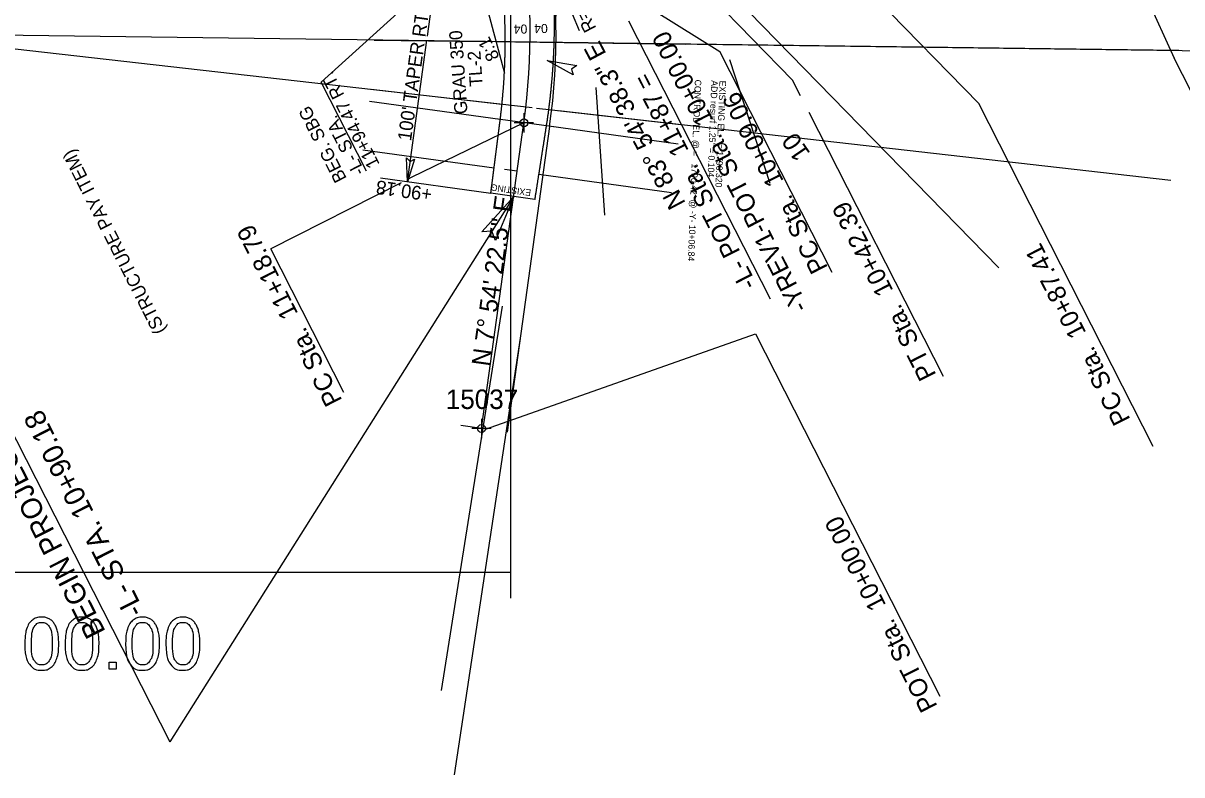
# Model space of a CAD drawing. Extents: x 557583 to 560285, y 513145 to 516544.
# Drawn here: x 559211.5 to 559657.8, y 515111.5 to 515400.9 of the extents above; entities that cross this region are included whole.
import ezdxf

# ---------------------------------------------------------------- set-up
doc = ezdxf.new("R2010")
doc.units = 0
for name, color, linetype in [('COGO Default Chain', 7, 'Continuous'), ('Default', 7, 'Continuous'), ('Exist Environmental Wetland Boundary', 7, 'Continuous'), ('Exist Environmental Wetland Boundary Cogo Comment', 7, 'Continuous'), ('Exist Environmental Wetland Boundary Cogo Point CELL', 7, 'Continuous'), ('Exist Hydro Jurisdictional Stream or Body of Water NEU Mitigable Cogo Comment', 7, 'Continuous'), ('Exist Hydro Jurisdictional Stream or Body of Water NEU Mitigable Cogo Elevation', 7, 'Continuous'), ('Exist Hydro Swamp or Marsh', 7, 'Continuous'), ('Prop Dimension', 7, 'Continuous'), ('Prop DSN Text', 7, 'Continuous'), ('Prop EOT', 7, 'Continuous'), ('Prop Guardrail Anchor Unit CELL', 7, 'Continuous'), ('Prop Paved Shoulder', 7, 'Continuous'), ('Prop Superelevation Label', 7, 'Continuous'), ('Prop Terminator CELL', 7, 'Continuous'), ('Scratch_Level_0', 7, 'Continuous'), ('Scratch_Level_2', 7, 'Continuous'), ('Scratch_Level_3', 7, 'Continuous'), ('Scratch_Level_4', 7, 'Continuous'), ('Scratch_Level_7', 7, 'Continuous'), ('Scratch_Level_8', 7, 'Continuous')]:
    doc.layers.add(name, color=color, linetype=linetype)

msp = doc.modelspace()

# ---------------------------------------------------------------- linework, layer by layer
at = {"layer": 'COGO Default Chain'}
for p, q in [((559404.4, 515366.25), (559404.4, 515358.75)), ((559408.15, 515362.5), (559400.65, 515362.5)), ((559388.06, 515248.59), (559388.06, 515241.09)), ((559391.81, 515244.84), (559384.31, 515244.84))]:
    msp.add_line(p, q, dxfattribs=at)
msp.add_arc((559156.78, 515396.89), 250, 352.0938, 26.9819, dxfattribs=at)
at = {"layer": 'Default'}
for p, q in [((559399.28, 515447.65), (559399.28, 515179.47)), ((559105.95, 515189.47), (559399.28, 515189.47))]:
    msp.add_line(p, q, dxfattribs=at)
at = {"layer": 'Exist Environmental Wetland Boundary'}
msp.add_line((559388.06, 515244.84), (559380.14, 515245.94), dxfattribs=at)
msp.add_line((559388.06, 515244.84), (559380.14, 515245.94), dxfattribs=at)
at = {"layer": 'Exist Environmental Wetland Boundary Cogo Point CELL'}
for p, q in [((559590.29, 515529.56), (559654.86, 515387.43)), ((559443.12, 515445.39), (559507.89, 515378.97)), ((559510.6, 515440.68), (559579.6, 515369.93)), ((559425.75, 515397.97), (559411.89, 515431.29)), ((559413.51, 515431.46), (559479.86, 515389.93)), ((559499.36, 515294.58), (559444.86, 515401.63)), ((559523.19, 515304.83), (559479.86, 515389.93)), ((559701.49, 515295.84), (559654.86, 515387.43)), ((559511, 515372.86), (559507.89, 515378.97)), ((559646.83, 515237.87), (559579.6, 515369.93)), ((559565.98, 515264.88), (559514.27, 515366.44)), ((559404.4, 515362.5), (559361, 515341.43)), ((559361, 515341.43), (559360.02, 515340.93)), ((559357.1, 515339.44), (559306.95, 515313.98)), ((559335.08, 515258.72), (559306.95, 515313.98)), ((559389.55, 515244.63), (559493.66, 515281.3)), ((559493.66, 515281.3), (559564.68, 515141.8))]:
    msp.add_line(p, q, dxfattribs=at)
for centre in [(559404.4, 515362.5), (559404.4, 515362.5), (559388.06, 515244.84), (559388.06, 515244.84), (559388.06, 515244.84)]:
    msp.add_circle(centre, 1.5, dxfattribs=at)
at = {"layer": 'Exist Hydro Jurisdictional Stream or Body of Water NEU Mitigable Cogo Elevation'}
msp.add_line((559388.06, 515244.84), (559404.4, 515362.5), dxfattribs=at)
msp.add_arc((559156.78, 515396.89), 250, 352.0938, 26.9819, dxfattribs=at)
at = {"layer": 'Exist Hydro Swamp or Marsh'}
msp.add_line((559401.81, 515343.89), (559396.86, 515344.58), dxfattribs=at)
msp.add_line((559401.81, 515343.89), (559396.86, 515344.58), dxfattribs=at)
at = {"layer": 'Prop Dimension'}
for p, q in [((559389.76, 515435.62), (559326.3, 515378.18)), ((559367.26, 515395.81), (559371.85, 515428.86)), ((559359.49, 515339.85), (559367.06, 515394.34)), ((559343.77, 515343.92), (559326.3, 515378.18)), ((559349.18, 515341.28), (559391.65, 515335.39)), ((559400.46, 515334.16), (559267.96, 515124.18)), ((559191.37, 515274.61), (559267.96, 515124.18))]:
    msp.add_line(p, q, dxfattribs=at)
at = {"layer": 'Prop DSN Text'}
for p, q in [((559404.4, 515366.25), (559404.4, 515358.75)), ((559408.15, 515362.5), (559400.65, 515362.5))]:
    msp.add_line(p, q, dxfattribs=at)
msp.add_arc((559156.78, 515396.89), 250, 352.0938, 26.9819, dxfattribs=at)
at = {"layer": 'Prop EOT'}
msp.add_line((559408.66, 515333.02), (559391.65, 515335.39), dxfattribs=at)
msp.add_arc((559448.16, 515398.31), 32, 115.7408, 179.4343, dxfattribs=at)
for points in [[(559415.56, 515383.31), (559415.61, 515384.01), (559415.65, 515384.71), (559415.7, 515385.41), (559415.74, 515386.1), (559415.78, 515386.8), (559415.82, 515387.5), (559415.85, 515388.2), (559415.89, 515388.9), (559415.92, 515389.6), (559415.95, 515390.3), (559415.98, 515391), (559416, 515391.7), (559416.03, 515392.4), (559416.05, 515393.11), (559416.07, 515393.81), (559416.09, 515394.51), (559416.11, 515395.21), (559416.12, 515395.91), (559416.14, 515396.61), (559416.15, 515397.31), (559416.16, 515398.01), (559416.17, 515398.71), (559416.17, 515399.41), (559416.17, 515400.11), (559416.18, 515400.82), (559416.18, 515401.52), (559416.17, 515402.22), (559416.17, 515402.92), (559416.17, 515403.62), (559416.16, 515404.32), (559416.15, 515405.02), (559416.14, 515405.73), (559416.12, 515406.43), (559416.11, 515407.13), (559416.09, 515407.83), (559416.07, 515408.53), (559416.05, 515409.23), (559416.03, 515409.93), (559416, 515410.63), (559415.98, 515411.34), (559415.95, 515412.04), (559415.92, 515412.74), (559415.89, 515413.44), (559415.85, 515414.14), (559415.82, 515414.84), (559415.78, 515415.54), (559415.74, 515416.24), (559415.7, 515416.94), (559415.65, 515417.64), (559415.61, 515418.34), (559415.56, 515419.04), (559415.51, 515419.75), (559415.46, 515420.45), (559415.41, 515421.15), (559415.35, 515421.85), (559415.3, 515422.55), (559415.24, 515423.25), (559415.18, 515423.95), (559415.11, 515424.64), (559415.05, 515425.34), (559414.98, 515426.04), (559414.92, 515426.74), (559414.85, 515427.44), (559414.77, 515428.14), (559414.7, 515428.84), (559414.62, 515429.54), (559414.55, 515430.24), (559414.47, 515430.93), (559414.39, 515431.63), (559414.3, 515432.33), (559414.22, 515433.03), (559414.13, 515433.72), (559413.95, 515435.12)], [(559397, 515384.28), (559397.02, 515384.93), (559397.05, 515385.58), (559397.07, 515386.23), (559397.09, 515386.88), (559397.11, 515387.53), (559397.12, 515388.18), (559397.14, 515388.83), (559397.15, 515389.48), (559397.16, 515390.13), (559397.17, 515390.78), (559397.18, 515391.43), (559397.19, 515392.08), (559397.19, 515392.73), (559397.2, 515393.38), (559397.2, 515394.03), (559397.2, 515394.68), (559397.19, 515395.33), (559397.19, 515395.98), (559397.18, 515396.63), (559397.18, 515397.28), (559397.17, 515397.93), (559397.16, 515398.58), (559397.14, 515399.23), (559397.13, 515399.88), (559397.11, 515400.53), (559397.09, 515401.18), (559397.07, 515401.83), (559397.05, 515402.48), (559397.03, 515403.12), (559397, 515403.77), (559396.98, 515404.42), (559396.95, 515405.07), (559396.92, 515405.72), (559396.89, 515406.37), (559396.85, 515407.02), (559396.82, 515407.67), (559396.78, 515408.31), (559396.74, 515408.96), (559396.7, 515409.61), (559396.66, 515410.26), (559396.61, 515410.91), (559396.57, 515411.55), (559396.52, 515412.2), (559396.47, 515412.85), (559396.42, 515413.5), (559396.36, 515414.14), (559396.31, 515414.79), (559396.25, 515415.44), (559396.19, 515416.08), (559396.13, 515416.73), (559396.07, 515417.38), (559396.01, 515418.02), (559395.94, 515418.67), (559395.88, 515419.31), (559395.81, 515419.96), (559395.74, 515420.6), (559395.66, 515421.25), (559395.59, 515421.89), (559395.51, 515422.54), (559395.44, 515423.18), (559395.36, 515423.83), (559395.28, 515424.47), (559395.19, 515425.11), (559395.11, 515425.76), (559395.02, 515426.4), (559394.93, 515427.04), (559394.84, 515427.69), (559394.75, 515428.33), (559394.66, 515428.97), (559394.56, 515429.61), (559394.47, 515430.25), (559394.37, 515430.9), (559394.17, 515432.18)], [(559391.65, 515335.39), (559391.73, 515336.06), (559391.82, 515336.73), (559391.91, 515337.4), (559391.99, 515338.07), (559392.08, 515338.74), (559392.16, 515339.41), (559392.25, 515340.08), (559392.33, 515340.75), (559392.42, 515341.42), (559392.5, 515342.09), (559392.59, 515342.76), (559392.68, 515343.43), (559392.76, 515344.1), (559392.85, 515344.77), (559392.93, 515345.44), (559393.02, 515346.11), (559393.1, 515346.78), (559393.19, 515347.45), (559393.27, 515348.12), (559393.36, 515348.79), (559393.45, 515349.46), (559393.53, 515350.13), (559393.62, 515350.8), (559393.7, 515351.47), (559393.79, 515352.14), (559393.87, 515352.81), (559393.96, 515353.48), (559394.04, 515354.15), (559394.13, 515354.82), (559394.22, 515355.49), (559394.3, 515356.17), (559394.39, 515356.84), (559394.47, 515357.51), (559394.56, 515358.18), (559394.64, 515358.85), (559394.73, 515359.52), (559394.82, 515360.19), (559394.9, 515360.86), (559394.99, 515361.53), (559395.07, 515362.2), (559395.16, 515362.87), (559395.24, 515363.54), (559395.33, 515364.19), (559395.41, 515364.84), (559395.48, 515365.48), (559395.56, 515366.13), (559395.64, 515366.78), (559395.71, 515367.42), (559395.78, 515368.07), (559395.85, 515368.72), (559395.92, 515369.36), (559395.98, 515370.01), (559396.05, 515370.66), (559396.11, 515371.31), (559396.17, 515371.95), (559396.23, 515372.6), (559396.29, 515373.25), (559396.34, 515373.9), (559396.4, 515374.55), (559396.45, 515375.19), (559396.5, 515375.84), (559396.55, 515376.49), (559396.6, 515377.14), (559396.64, 515377.79), (559396.68, 515378.44), (559396.73, 515379.09), (559396.77, 515379.74), (559396.8, 515380.39), (559396.84, 515381.03), (559396.87, 515381.68), (559396.91, 515382.33), (559396.94, 515382.98), (559396.97, 515383.63), (559397, 515384.28)], [(559408.67, 515333.02), (559408.77, 515333.69), (559408.87, 515334.36), (559408.98, 515335.03), (559409.08, 515335.69), (559409.19, 515336.36), (559409.29, 515337.03), (559409.4, 515337.7), (559409.5, 515338.36), (559409.61, 515339.03), (559409.71, 515339.7), (559409.81, 515340.37), (559409.92, 515341.04), (559410.02, 515341.7), (559410.13, 515342.37), (559410.23, 515343.04), (559410.34, 515343.71), (559410.44, 515344.37), (559410.55, 515345.04), (559410.65, 515345.71), (559410.75, 515346.38), (559410.86, 515347.04), (559410.96, 515347.71), (559411.07, 515348.38), (559411.17, 515349.05), (559411.28, 515349.71), (559411.38, 515350.38), (559411.49, 515351.05), (559411.59, 515351.72), (559411.69, 515352.39), (559411.8, 515353.05), (559411.9, 515353.72), (559412.01, 515354.39), (559412.11, 515355.06), (559412.22, 515355.72), (559412.32, 515356.39), (559412.43, 515357.06), (559412.53, 515357.73), (559412.63, 515358.39), (559412.74, 515359.06), (559412.84, 515359.73), (559412.95, 515360.4), (559413.05, 515361.07), (559413.16, 515361.75), (559413.26, 515362.44), (559413.37, 515363.13), (559413.47, 515363.82), (559413.57, 515364.52), (559413.67, 515365.21), (559413.76, 515365.9), (559413.86, 515366.6), (559413.95, 515367.29), (559414.04, 515367.98), (559414.13, 515368.68), (559414.22, 515369.37), (559414.3, 515370.07), (559414.39, 515370.76), (559414.47, 515371.46), (559414.55, 515372.15), (559414.62, 515372.85), (559414.7, 515373.54), (559414.77, 515374.24), (559414.84, 515374.94), (559414.91, 515375.63), (559414.98, 515376.33), (559415.05, 515377.03), (559415.11, 515377.72), (559415.18, 515378.42), (559415.24, 515379.12), (559415.29, 515379.82), (559415.35, 515380.51), (559415.41, 515381.21), (559415.46, 515381.91), (559415.51, 515382.61), (559415.56, 515383.31)]]:
    msp.add_spline(points, degree=3, dxfattribs=at)
at = {"layer": 'Prop Paved Shoulder'}
msp.add_line((559390.29, 515406.56), (559396.87, 515381.68), dxfattribs=at)
at = {"layer": 'Prop Terminator CELL'}
for points in [[(559362.27, 515348.55), (559359.49, 515339.85), (559359.15, 515349.04), (559360.58, 515347.68)], [(559388.24, 515320.59), (559400.46, 515334.16), (559393.51, 515317.15), (559392.03, 515320.8)]]:
    msp.add_lwpolyline(points, close=True, dxfattribs=at)
at = {"layer": 'Scratch_Level_0'}
msp.add_lwpolyline([(559244.58, 515152.12), (559244.58, 515154.91), (559247.37, 515154.91), (559247.37, 515152.12), (559244.58, 515152.12)], dxfattribs=at)
for points in [[(559212.14, 515161.98), (559212.14, 515165.53), (559212.87, 515167.69), (559213.6, 515169.86), (559215.04, 515171.03), (559216.48, 515172.19), (559218.66, 515172.19), (559220.27, 515172.19), (559221.49, 515171.55), (559222.7, 515170.9), (559223.49, 515169.68), (559224.28, 515168.46), (559224.73, 515166.71), (559225.18, 515164.95), (559225.18, 515161.98), (559225.18, 515158.46), (559224.45, 515156.3), (559223.73, 515154.13), (559222.29, 515152.96), (559220.86, 515151.78), (559218.66, 515151.78), (559215.77, 515151.78), (559214.12, 515153.85), (559212.14, 515156.35), (559212.14, 515161.98)], [(559227.68, 515161.98), (559227.68, 515165.53), (559228.41, 515167.69), (559229.14, 515169.86), (559230.57, 515171.03), (559232.01, 515172.19), (559234.19, 515172.19), (559235.8, 515172.19), (559237.02, 515171.55), (559238.24, 515170.9), (559239.02, 515169.68), (559239.81, 515168.46), (559240.26, 515166.71), (559240.71, 515164.95), (559240.71, 515161.98), (559240.71, 515158.46), (559239.99, 515156.3), (559239.27, 515154.13), (559237.83, 515152.96), (559236.39, 515151.78), (559234.19, 515151.78), (559231.3, 515151.78), (559229.65, 515153.85), (559227.68, 515156.35), (559227.68, 515161.98)], [(559250.97, 515161.98), (559250.97, 515165.53), (559251.7, 515167.69), (559252.43, 515169.86), (559253.87, 515171.03), (559255.31, 515172.19), (559257.49, 515172.19), (559259.1, 515172.19), (559260.31, 515171.55), (559261.53, 515170.9), (559262.32, 515169.68), (559263.1, 515168.46), (559263.55, 515166.71), (559264, 515164.95), (559264, 515161.98), (559264, 515158.46), (559263.28, 515156.3), (559262.56, 515154.13), (559261.12, 515152.96), (559259.68, 515151.78), (559257.49, 515151.78), (559254.6, 515151.78), (559252.95, 515153.85), (559250.97, 515156.35), (559250.97, 515161.98)], [(559266.5, 515161.98), (559266.5, 515165.53), (559267.23, 515167.69), (559267.96, 515169.86), (559269.4, 515171.03), (559270.84, 515172.19), (559273.02, 515172.19), (559274.63, 515172.19), (559275.85, 515171.55), (559277.06, 515170.9), (559277.85, 515169.68), (559278.64, 515168.46), (559279.09, 515166.71), (559279.54, 515164.95), (559279.54, 515161.98), (559279.54, 515158.46), (559278.81, 515156.3), (559278.09, 515154.13), (559276.65, 515152.96), (559275.22, 515151.78), (559273.02, 515151.78), (559270.13, 515151.78), (559268.48, 515153.85), (559266.5, 515156.35), (559266.5, 515161.98)], [(559214.67, 515161.98), (559214.67, 515157.05), (559215.82, 515155.42), (559216.97, 515153.8), (559218.66, 515153.8), (559220.35, 515153.8), (559221.5, 515155.43), (559222.65, 515157.06), (559222.65, 515161.98), (559222.65, 515166.92), (559221.5, 515168.54), (559220.35, 515170.17), (559218.63, 515170.17), (559216.95, 515170.17), (559215.94, 515168.73), (559214.67, 515166.91), (559214.67, 515161.98)], [(559230.21, 515161.98), (559230.21, 515157.05), (559231.36, 515155.42), (559232.51, 515153.8), (559234.19, 515153.8), (559235.88, 515153.8), (559237.03, 515155.43), (559238.18, 515157.06), (559238.18, 515161.98), (559238.18, 515166.92), (559237.03, 515168.54), (559235.88, 515170.17), (559234.17, 515170.17), (559232.48, 515170.17), (559231.47, 515168.73), (559230.21, 515166.91), (559230.21, 515161.98)], [(559253.5, 515161.98), (559253.5, 515157.05), (559254.65, 515155.42), (559255.8, 515153.8), (559257.49, 515153.8), (559259.17, 515153.8), (559260.32, 515155.43), (559261.47, 515157.06), (559261.47, 515161.98), (559261.47, 515166.92), (559260.33, 515168.54), (559259.18, 515170.17), (559257.46, 515170.17), (559255.77, 515170.17), (559254.76, 515168.73), (559253.5, 515166.91), (559253.5, 515161.98)], [(559269.03, 515161.98), (559269.03, 515157.05), (559270.18, 515155.42), (559271.33, 515153.8), (559273.02, 515153.8), (559274.71, 515153.8), (559275.86, 515155.43), (559277.01, 515157.06), (559277.01, 515161.98), (559277.01, 515166.92), (559275.86, 515168.54), (559274.71, 515170.17), (559272.99, 515170.17), (559271.31, 515170.17), (559270.3, 515168.73), (559269.03, 515166.91), (559269.03, 515161.98)]]:
    msp.add_open_spline(points, degree=3, dxfattribs=at)
at = {"layer": 'Scratch_Level_2'}
for p, q in [((559156.78, 515396.89), (559407.6, 515368.39)), ((559656.73, 515390.31), (559156.78, 515396.89)), ((559409.24, 515368.2), (559415.11, 515367.53)), ((559415.81, 515360.92), (559394.49, 515363.88)), ((559417.67, 515367.24), (559653.58, 515340.43))]:
    msp.add_line(p, q, dxfattribs=at)
msp.add_arc((559156.78, 515396.89), 260, 352.0938, 26.9819, dxfattribs=at)
at = {"layer": 'Scratch_Level_3'}
for p, q in [((559587.3, 515306.64), (559308.02, 515593)), ((559414.3, 515361.12), (559397.96, 515243.46)), ((559372.63, 515143.91), (559396.14, 515291.97)), ((559377.67, 515111.51), (559403.08, 515279.57))]:
    msp.add_line(p, q, dxfattribs=at)
msp.add_lwpolyline([(559423.38, 515380.92), (559413.4, 515386.46), (559424.74, 515384.62), (559422.72, 515383.21)], close=True, dxfattribs=at)
msp.add_arc((559156.78, 515396.89), 260, 352.0938, 26.9819, dxfattribs=at)
at = {"layer": 'Scratch_Level_4'}
for p, q in [((559346.76, 515394.39), (559388.4, 515393.84)), ((559393.67, 515393.77), (559397.2, 515393.73)), ((559393.67, 515393.77), (559400.64, 515393.68)), ((559401.11, 515393.68), (559466.75, 515392.81)), ((559402.36, 515393.66), (560206.69, 515383.08))]:
    msp.add_line(p, q, dxfattribs=at)
at = {"layer": 'Scratch_Level_7'}
for p, q in [((559397.2, 515393.73), (559346.76, 515394.39)), ((559466.75, 515392.81), (559416.06, 515393.48)), ((559483.62, 515386.85), (559499.19, 515339.33)), ((559345.56, 515375.44), (559395.95, 515369.71)), ((559435.55, 515326.98), (559432.27, 515376.15)), ((559395.27, 515363.77), (559344.97, 515370.75)), ((559414, 515367.66), (559464.79, 515361.89)), ((559463.83, 515354.25), (559413.09, 515361.29)), ((559342.39, 515352.14), (559392.89, 515345.13)), ((559410.18, 515342.73), (559461.24, 515335.64))]:
    msp.add_line(p, q, dxfattribs=at)
at = {"layer": 'Scratch_Level_8'}
msp.add_line((559408.68, 515332.98), (559408.66, 515333.03), dxfattribs=at)

# ---------------------------------------------------------------- texts
at = {"layer": 'COGO Default Chain'}
msp.add_text('15037', height=7.5, dxfattribs=at).set_placement((559374.3, 515252.34))
at = {"layer": 'Exist Environmental Wetland Boundary Cogo Comment'}
msp.add_text('10', height=7, rotation=124.3572, dxfattribs=at).set_placement((559514.95, 515350.78))
at = {"layer": 'Exist Environmental Wetland Boundary Cogo Point CELL'}
for s, p in [('-YREV1-POT Sta.  10+00.00', (559514.13, 515291.64)), ('-L- POT Sta.  11+87 =', (559494.27, 515300.33)), ('PC Sta.  10+09.06', (559521.64, 515306.71)), ('PT Sta.  10+42.39', (559563.37, 515265.48)), ('PC Sta.  11+18.79', (559334.56, 515255.65)), ('PC Sta.  10+87.41', (559638.15, 515248.3)), ('POT Sta.  10+00.00', (559563.88, 515137.89))]:
    msp.add_text(s, height=7, rotation=116.9819, dxfattribs=at).set_placement(p)
at = {"layer": 'Exist Hydro Jurisdictional Stream or Body of Water NEU Mitigable Cogo Comment'}
for s, rotation, p in [('N 83%%d 54\' 38.3" E', 117.9873, (559466.86, 515331.57)), ('N 7%%d 54\' 22.5" E', 82.0938, (559391.14, 515268.49))]:
    msp.add_text(s, height=7, rotation=rotation, dxfattribs=at).set_placement(p)
at = {"layer": 'Prop Dimension'}
for s, height, rotation, p in [("100' TAPER RT. & LT.", 5.25, 82.0938, (559360.9, 515355.28)), ("R=30'", 5, 117.5992, (559432.38, 515398.98)), ('8:1', 5, 116.9819, (559395.13, 515387.8)), ('(STRUCTURE PAY ITEM) ', 5, 116.9819, (559266.59, 515282.63)), ('+90.18', 5.25, 172.0938, (559369.31, 515337.4))]:
    msp.add_text(s, height=height, rotation=rotation, dxfattribs=at).set_placement(p)
at = {"layer": 'Prop DSN Text'}
for s, height, rotation, p in [('11+94.47 RT.', 5, 117.0233, (559348.96, 515346.57)), ('BEG. SBG', 5, 117.0233, (559336.25, 515341.09)), ('-L- STA. ', 5, 117.0233, (559343.31, 515343.69)), ('EXISTING', 2.5, 172.0938, (559407.28, 515336.79)), ('BEGIN PROJECT B-4734', 8, 116.9819, (559243.4, 515166.63)), ('-L- STA. 10+90.18', 8, 116.9819, (559258.28, 515174.56))]:
    msp.add_text(s, height=height, rotation=rotation, dxfattribs=at).set_placement(p)
at = {"layer": 'Prop Guardrail Anchor Unit CELL'}
for s, p in [('GRAU 350', (559382.7, 515366)), (' TL-2', (559388.67, 515374.81))]:
    msp.add_text(s, height=5, rotation=93.8764, dxfattribs=at).set_placement(p)
at = {"layer": 'Prop Superelevation Label'}
for p in [(559405.68, 515400.38), (559413.55, 515400.6)]:
    msp.add_text('04', height=3.5, rotation=181.0037, dxfattribs=at).set_placement(p)
at = {"layer": 'Scratch_Level_3'}
for s, p in [('CONTROL EL. @ =   1790.42  @ -Y- 10+06.84', (559470.27, 515379.18)), ('ADD resurf 1.25" = 0.104', (559476.61, 515378.93)), ('EXISTING EL.   = 1790.320', (559479.77, 515378.81))]:
    msp.add_text(s, height=2.5, rotation=267.7628, dxfattribs=at).set_placement(p)

doc.saveas('drawing.dxf')
